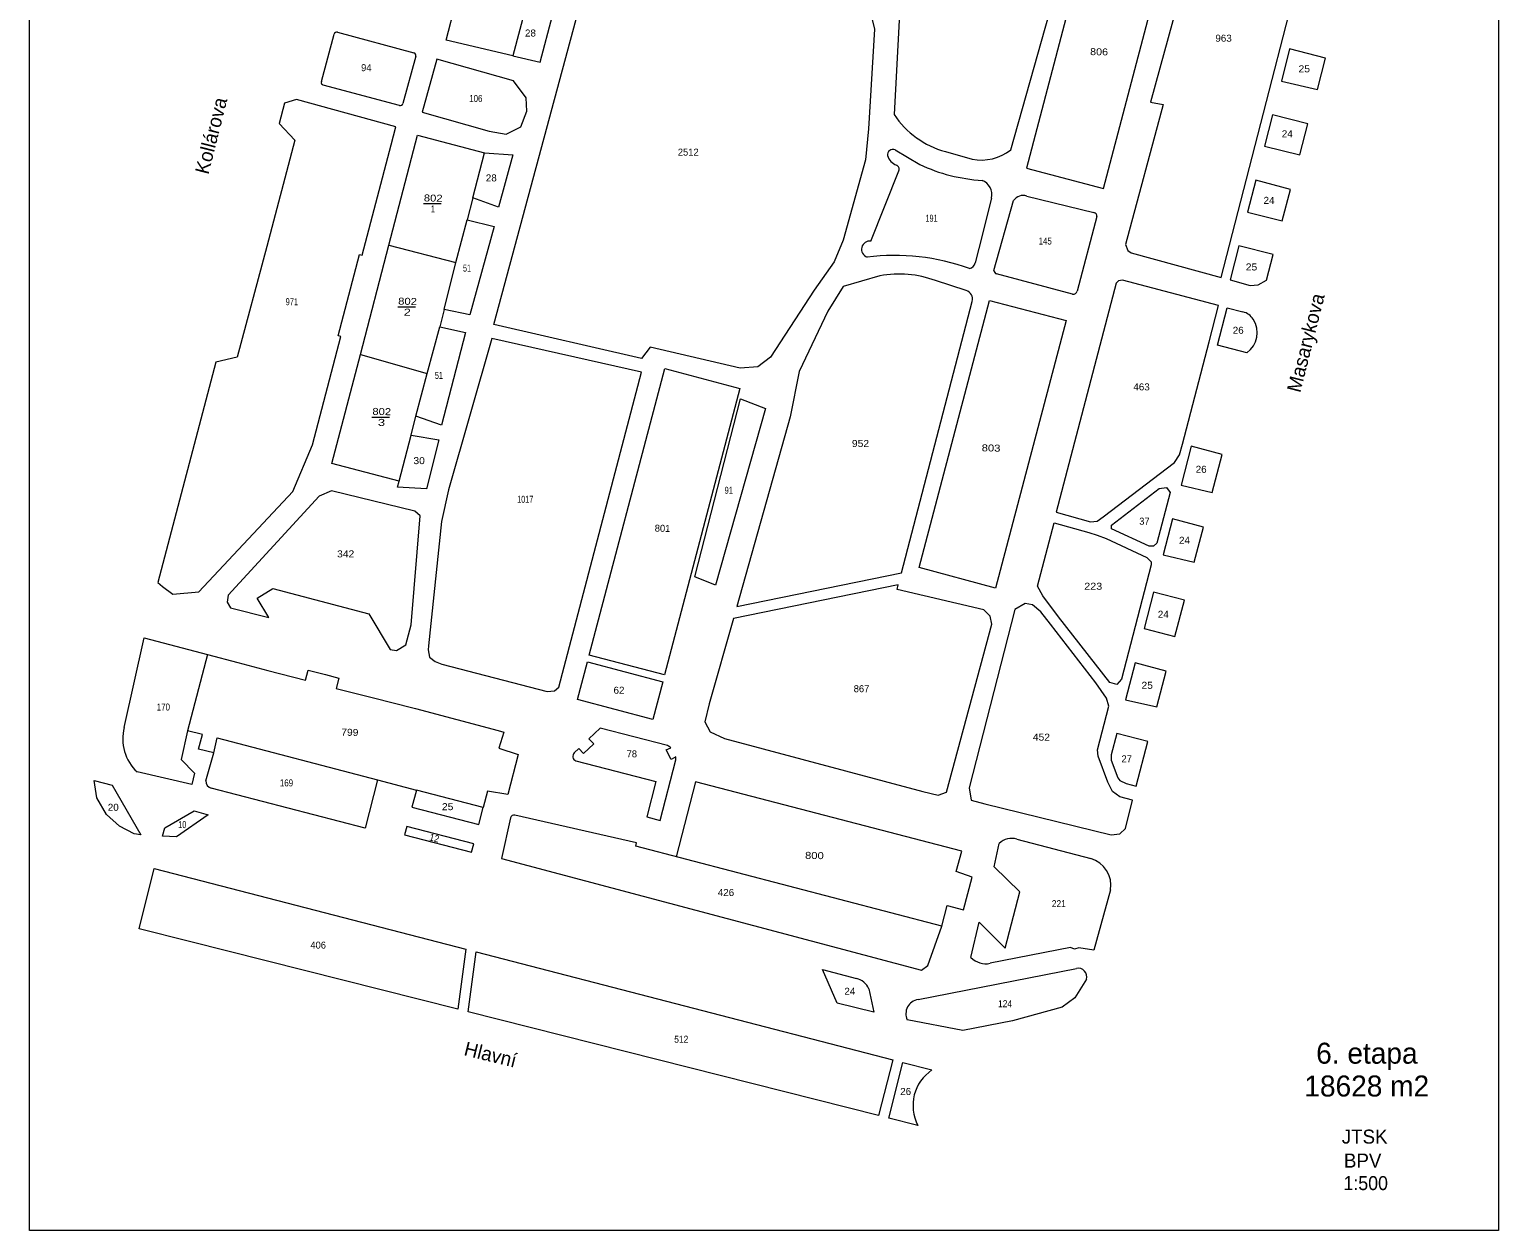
# Model space of a CAD drawing. Extents: x -843471 to -843261, y -1003203 to -1002905.
# Drawn here: x -843471 to -843261, y -1003202.7 to -1003031 of the extents above; entities that cross this region are included whole.
import ezdxf
from ezdxf.enums import TextEntityAlignment as Align

# ---------------------------------------------------------------- set-up
doc = ezdxf.new("R2010")
doc.units = 0
doc.header["$LTSCALE"] = 0.4
doc.layers.add('20', color=7, linetype='Continuous')
for name, color, linetype, lineweight in [('35', 7, 'Continuous', 13), ('38', 7, 'Continuous', 13), ('43', 7, 'Continuous', 13), ('44', 7, 'Continuous', 13), ('63', 7, 'Continuous', 13)]:
    doc.layers.add(name, color=color, linetype=linetype, lineweight=lineweight)

msp = doc.modelspace()

# ---------------------------------------------------------------- linework, layer by layer
at = {"layer": '35'}
for p, q in [((-843414.648, -1003055.883), (-843412.134, -1003055.883)), ((-843418.312, -1003070.638), (-843415.798, -1003070.638)), ((-843422.003, -1003086.395), (-843419.489, -1003086.395))]:
    msp.add_line(p, q, dxfattribs=at)
at = {"layer": '38'}
for p, q in [((-843415.48, -1003046.07), (-843405.92, -1003048.64)), ((-843407.59, -1003055.07), (-843408.4, -1003058.18)), ((-843419.59, -1003061.82), (-843410, -1003064.31)), ((-843411.69, -1003071.03), (-843412.32, -1003073.51)), ((-843423.66, -1003077.43), (-843414.12, -1003080.14)), ((-843416.41, -1003088.95), (-843415.71, -1003086.25)), ((-843421.233, -1003138.239), (-843415.655, -1003139.692))]:
    msp.add_line(p, q, dxfattribs=at)
for points in [[(-843401.85, -1003034.75), (-843411.41, -1003032.51), (-843407.25, -1003016.45), (-843403.17, -1003000.7), (-843399.16, -1002985.21), (-843389.38, -1002987.7)], [(-843418.13, -1003095.53), (-843427.74, -1003093.04), (-843423.66, -1003077.43), (-843419.59, -1003061.82), (-843415.48, -1003046.07)], [(-843445.52, -1003120.31), (-843441.17, -1003121.48), (-843436.9, -1003122.6), (-843431.5, -1003124.01), (-843431.12, -1003122.55), (-843428.65, -1003123.2), (-843426.72, -1003123.7), (-843427.1, -1003125.16), (-843421.38, -1003126.62), (-843419.36, -1003127.13), (-843415.77, -1003128.04), (-843403.96, -1003131.2), (-843403.16, -1003131.41), (-843403.87, -1003133.7), (-843401.1, -1003134.61), (-843402.58, -1003140.34), (-843405.473, -1003139.847), (-843406.09, -1003142.2)], [(-843444.62, -1003134.38), (-843446.8, -1003133.85), (-843446.21, -1003131.74), (-843448.38, -1003131.22)], [(-843340.54, -1003159.16), (-843339.77, -1003156.2), (-843337.44, -1003156.8), (-843336.19, -1003152.17), (-843338.49, -1003151.35), (-843337.67, -1003148.41), (-843375.75, -1003138.54), (-843378.53, -1003149.26)]]:
    msp.add_lwpolyline(points, dxfattribs=at)
for points in [[(-843328.45, -1003050.8), (-843317.44, -1003053.71), (-843307.34, -1003015.31), (-843311.55, -1003014.24), (-843314.18, -1003013.56), (-843318.38, -1003012.49)], [(-843333.74, -1003069.74), (-843322.76, -1003072.57), (-843332.86, -1003110.84), (-843343.79, -1003107.9)], [(-843380.17, -1003123.25), (-843390.96, -1003120.41), (-843380.61, -1003081.27), (-843380.13, -1003079.45), (-843369.44, -1003082.32)]]:
    msp.add_lwpolyline(points, close=True, dxfattribs=at)
at = {"layer": '43'}
for p, q in [((-843426.921, -1003031.39), (-843416.036, -1003034.326)), ((-843429.236, -1003038.434), (-843427.412, -1003031.672)), ((-843415.754, -1003034.816), (-843417.578, -1003041.578)), ((-843418.069, -1003041.86), (-843428.954, -1003038.924)), ((-843347.22, -1003048.18), (-843343.689, -1003050.295)), ((-843340.04, -1003048.43), (-843336.23, -1003049.51)), ((-843350.678, -1003061.242), (-843346.68, -1003051.19)), ((-843333.11, -1003065.43), (-843330.3, -1003055.45)), ((-843328.399, -1003054.801), (-843318.83, -1003057.14)), ((-843318.38, -1003057.71), (-843321.22, -1003068.4)), ((-843334.757, -1003060.227), (-843335.79, -1003064.36)), ((-843337.054, -1003068.297), (-843341.457, -1003066.878)), ((-843321.86, -1003068.82), (-843332.72, -1003065.92)), ((-843346.332, -1003108.655), (-843336.201, -1003069.851)), ((-843296.958, -1003077.188), (-843301.14, -1003076.09)), ((-843379.929, -1003133.964), (-843379.278, -1003133.638)), ((-843402.18, -1003143.65), (-843403.502, -1003149.498)), ((-843329.84, -1003146.7), (-843319.25, -1003149.5)), ((-843316.42, -1003153.97), (-843318.81, -1003162.58)), ((-843357.599, -1003165.361), (-843352.759, -1003166.612)), ((-843343.95, -1003169.65), (-843321.305, -1003165.185)), ((-843346.118, -1003178.626), (-843341.955, -1003179.704))]:
    msp.add_line(p, q, dxfattribs=at)
for points in [[(-843284.45, -1003003.7), (-843294.7, -1003000.64), (-843296.31, -1003001.22), (-843302.99, -1003013.24), (-843302.99, -1003013.24), (-843310.734, -1003041.383), (-843308.91, -1003041.72), (-843314.3, -1003061.74), (-843313.983, -1003062.586), (-843313.47, -1003062.92), (-843300.63, -1003066.44)], [(-843388.71, -1003014.29), (-843366.28, -1003020.43), (-843366.73, -1003022), (-843353.17, -1003025.55), (-843351, -1003027.64), (-843350.16, -1003030.95), (-843351.05, -1003045.19), (-843351.48, -1003049.64), (-843354.64, -1003061.08), (-843355.93, -1003064.18), (-843358.81, -1003068.24), (-843365.03, -1003077.8), (-843366.86, -1003079.21), (-843369.37, -1003079.38), (-843382.26, -1003076.4), (-843383.48, -1003078.02), (-843404.56, -1003073.14)], [(-843401.85, -1003034.75), (-843397.955, -1003035.663), (-843396.184, -1003028.978), (-843400.046, -1003027.953)], [(-843414.849, -1003042.812), (-843405.27, -1003045.53), (-843402.84, -1003045.94), (-843400.71, -1003044.91), (-843399.86, -1003042.66), (-843399.95, -1003040.76), (-843401.767, -1003038.337), (-843412.722, -1003035.254)], [(-843292.02, -1003038.36), (-843286.864, -1003039.586), (-843285.692, -1003035.093), (-843290.85, -1003033.77)], [(-843418.595, -1003044.919), (-843432.78, -1003041), (-843434.5, -1003041.54), (-843435.263, -1003044.448), (-843433.02, -1003046.81), (-843437.05, -1003062), (-843441.25, -1003077.83), (-843444.331, -1003078.56), (-843452.6, -1003110.03), (-843451.96, -1003110.61), (-843450.48, -1003111.71), (-843446.75, -1003111.38), (-843433.29, -1003097.02), (-843430.48, -1003090.34), (-843426.437, -1003074.888), (-843426.844, -1003074.782), (-843423.8, -1003063.15), (-843423.393, -1003063.256), (-843419.26, -1003047.46)], [(-843294.41, -1003047.68), (-843289.4, -1003048.9), (-843288.23, -1003044.49), (-843293.27, -1003043.2)], [(-843405.92, -1003048.64), (-843401.85, -1003048.89), (-843403.9, -1003056.39), (-843407.59, -1003055.07)], [(-843296.84, -1003057.1), (-843291.9, -1003058.32), (-843290.72, -1003053.87), (-843295.67, -1003052.53)], [(-843408.4, -1003058.18), (-843404.53, -1003059.14), (-843408.01, -1003071.76), (-843411.69, -1003071.03), (-843410, -1003064.31)], [(-843293.19, -1003063.17), (-843298.1, -1003061.92), (-843299.36, -1003066.78), (-843296.46, -1003067.56), (-843295.35, -1003067.49), (-843294.16, -1003066.84)], [(-843324.229, -1003099.954), (-843319.32, -1003101.34), (-843318.36, -1003101.24), (-843317.5, -1003100.634), (-843307.27, -1003092.87), (-843306.57, -1003091.79), (-843306.14, -1003090.26), (-843302.35, -1003075.63), (-843301.02, -1003070.45), (-843314.74, -1003066.83), (-843315.278, -1003066.897), (-843315.622, -1003067.26)], [(-843414.12, -1003080.14), (-843412.32, -1003073.51), (-843408.65, -1003074.31), (-843412.04, -1003087.56), (-843415.71, -1003086.25)], [(-843413.78, -1003120.71), (-843412.95, -1003121.33), (-843412.02, -1003121.68), (-843396.96, -1003125.61), (-843395.92, -1003125.51), (-843395.27, -1003124.99), (-843383.48, -1003079.99), (-843404.86, -1003075.14), (-843411.06, -1003096.77), (-843412.06, -1003101.33), (-843413.9, -1003119.1), (-843413.96, -1003119.64)], [(-843369.333, -1003083.797), (-843365.77, -1003085.15), (-843372.91, -1003110.39), (-843375.835, -1003109.243)], [(-843416.41, -1003088.95), (-843412.46, -1003089.64), (-843414.23, -1003096.66), (-843418.37, -1003096.41), (-843418.13, -1003095.53)], [(-843306.32, -1003096.1), (-843301.9, -1003097.17), (-843300.49, -1003091.73), (-843304.9, -1003090.56)], [(-843316.32, -1003102.34), (-843316.31, -1003101.85), (-843309.48, -1003096.59), (-843308.44, -1003096.44), (-843307.93, -1003097.18), (-843309.81, -1003104.42), (-843310.29, -1003104.84), (-843310.9, -1003104.86)], [(-843442.7, -1003112.85), (-843442.2, -1003113.65), (-843436.76, -1003115.04), (-843438.41, -1003112.27), (-843436.19, -1003110.91), (-843422.47, -1003114.51), (-843419.4, -1003119.61), (-843418.51, -1003119.73), (-843417.17, -1003118.92), (-843416.41, -1003116.09), (-843415.11, -1003100.52), (-843415.86, -1003099.84), (-843427.79, -1003096.94), (-843429.54, -1003097.71), (-843442.56, -1003111.82)], [(-843324.49, -1003101.48), (-843319.53, -1003102.9), (-843318.37, -1003103.25), (-843317.05, -1003103.75), (-843311.25, -1003106.46), (-843310.61, -1003107.08), (-843310.63, -1003107.51), (-843314.85, -1003123.86), (-843315.53, -1003124.6), (-843316.52, -1003124.32), (-843323.85, -1003114.96), (-843326.1, -1003111.92), (-843326.89, -1003110.55)], [(-843308.91, -1003106.06), (-843304.47, -1003107.12), (-843303.17, -1003102.11), (-843307.59, -1003100.91)], [(-843370.347, -1003115.171), (-843373.79, -1003127.38), (-843374.43, -1003129.93), (-843373.65, -1003131.37), (-843371.63, -1003132.33), (-843343.25, -1003139.88), (-843341.08, -1003140.44), (-843339.89, -1003140), (-843333.4, -1003115.97), (-843333.63, -1003114.83), (-843334.54, -1003113.93), (-843346.954, -1003111.038), (-843346.782, -1003110.379)], [(-843313.29, -1003141.15), (-843315.09, -1003140.66), (-843316.14, -1003139.9), (-843316.82, -1003138.56), (-843318.22, -1003134.85), (-843318.29, -1003133.97), (-843316.66, -1003127.71), (-843317.02, -1003126.54), (-843318.52, -1003124.37), (-843325.04, -1003116), (-843326.41, -1003114.24), (-843327.59, -1003113.23), (-843328.661, -1003113.027), (-843330.11, -1003113.91), (-843336.63, -1003139.36), (-843336.37, -1003141.15), (-843334.4, -1003141.67), (-843316.351, -1003146.08), (-843315.127, -1003145.939), (-843314.28, -1003145.19)], [(-843311.62, -1003116.6), (-843307.23, -1003117.75), (-843305.88, -1003112.55), (-843310.29, -1003111.39)], [(-843380.426, -1003124.217), (-843381.856, -1003129.626), (-843392.643, -1003126.773), (-843391.216, -1003121.377)], [(-843314.29, -1003126.79), (-843309.83, -1003127.81), (-843308.5, -1003122.68), (-843312.9, -1003121.52)], [(-843315.55, -1003131.61), (-843316.35, -1003134.68), (-843316.33, -1003135.43), (-843315.37, -1003137.97), (-843315.11, -1003138.31), (-843314.21, -1003138.77), (-843312.77, -1003139.14), (-843311.12, -1003132.77)], [(-843461.71, -1003138.35), (-843459.13, -1003138.99), (-843455.03, -1003146.09), (-843456.01, -1003145.97), (-843458.1, -1003144.87), (-843459.96, -1003143.19), (-843461.34, -1003140.83)], [(-843406.09, -1003142.2), (-843415.655, -1003139.692), (-843416.295, -1003142.132), (-843406.73, -1003144.64)], [(-843445.397, -1003143.229), (-843449.938, -1003146.368), (-843451.94, -1003146.29), (-843451.62, -1003145.1), (-843447.411, -1003142.685)], [(-843407.453, -1003147.399), (-843417.019, -1003144.89), (-843417.331, -1003146.082), (-843407.766, -1003148.59)], [(-843453.108, -1003150.917), (-843446.3, -1003152.68), (-843408.577, -1003162.45), (-843409.71, -1003171.023), (-843448.1, -1003161.33), (-843455.28, -1003159.517)], [(-843407.114, -1003162.829), (-843347.57, -1003178.25), (-843349.579, -1003186.206), (-843408.246, -1003171.393)]]:
    msp.add_lwpolyline(points, close=True, dxfattribs=at)
for points in [[(-843330.68, -1003048.19), (-843320.79, -1003013.05), (-843321.09, -1003011.86), (-843322.66, -1003011.55), (-843340.18, -1003010.64), (-843342.33, -1003011.23), (-843343.75, -1003012.82), (-843346.29, -1003023.32), (-843346.64, -1003029.65), (-843347.37, -1003043.16)], [(-843333.47, -1003055.08), (-843334.506, -1003059.225), (-843334.757, -1003060.227)], [(-843349.39, -1003066.18), (-843354.65, -1003067.73), (-843356.85, -1003071.23), (-843360.96, -1003079.89), (-843362.22, -1003086.35), (-843369.859, -1003113.439), (-843346.332, -1003108.655)], [(-843301.14, -1003076.09), (-843299.742, -1003070.764), (-843297.51, -1003071.35)], [(-843457.408, -1003130.736), (-843454.56, -1003117.95), (-843445.52, -1003120.31), (-843448.38, -1003131.22), (-843449.265, -1003135.312)], [(-843379.741, -1003133.34), (-843389.38, -1003130.857), (-843390.986, -1003132.384), (-843390.297, -1003133.109), (-843391.746, -1003134.487), (-843392.435, -1003133.762), (-843393.077, -1003134.372)], [(-843445.724, -1003138.384), (-843444.62, -1003134.38), (-843444.11, -1003132.23), (-843421.233, -1003138.239)], [(-843378.57, -1003134.961), (-843379.257, -1003135.305), (-843379.929, -1003133.964)], [(-843449.265, -1003135.312), (-843447.367, -1003137.265), (-843447.766, -1003138.888), (-843455.565, -1003137.108)], [(-843392.869, -1003135.521), (-843381.423, -1003138.47), (-843382.725, -1003143.527), (-843380.788, -1003144.026), (-843378.564, -1003135.391)], [(-843421.233, -1003138.239), (-843422.992, -1003145.123), (-843444.97, -1003139.41)], [(-843403.502, -1003149.498), (-843343.445, -1003165.446), (-843342.55, -1003164.79), (-843340.54, -1003159.16), (-843384.306, -1003147.723), (-843384.2, -1003147.26), (-843401.581, -1003143.275)], [(-843336.41, -1003163.63), (-843335.23, -1003158.59), (-843331.5, -1003162.3), (-843329.41, -1003154.24), (-843333.05, -1003150.65), (-843332.352, -1003147.312)], [(-843318.81, -1003162.58), (-843320.972, -1003162.24), (-843321.58, -1003162.46), (-843322.18, -1003162.21), (-843333.63, -1003164.46)], [(-843350.966, -1003168.096), (-843350.258, -1003171.421), (-843355.51, -1003170.166), (-843357.599, -1003165.361)], [(-843319.88, -1003166.73), (-843321.52, -1003169.41), (-843323.33, -1003170.71), (-843330.43, -1003172.68)], [(-843330.43, -1003172.68), (-843337.53, -1003174.06), (-843345.486, -1003172.535)], [(-843343.956, -1003187.626), (-843348.125, -1003186.574), (-843346.118, -1003178.626)]]:
    msp.add_lwpolyline(points, dxfattribs=at)
for centre, radius, start, end in [((-843427.0256, -1003031.7758), 0.4, 74.90421, 164.90421), ((-843416.1404, -1003034.712), 0.4, 344.90421, 74.90421), ((-843428.8496, -1003038.538), 0.4, 164.90421, 254.90421), ((-843417.9644, -1003041.4742), 0.4, 254.90421, 344.90421), ((-843336.6594, -1003035.9953), 12.8861, 213.77993, 254.79058), ((-843347.5123, -1003048.9279), 0.803, 68.65352, 186.5852), ((-843334.8795, -1003042.8592), 6.7863, 258.51965, 308.23051), ((-843346.3573, -1003048.4718), 2.0282, 195.68124, 250.18289), ((-843333.3754, -1003028.282), 24.3098, 244.89511, 266.64033), ((-843347.2545, -1003050.9615), 0.6182, 338.31208, 70.18289), ((-843335.5515, -1003054.5596), 2.1455, 345.96376, 69.49731), ((-843328.9497, -1003056.2978), 1.5944, 69.80983, 147.87639), ((-843318.9701, -1003057.7132), 0.5901, 0.31338, 76.26695), ((-843350.8442, -1003062.4124), 1.1823, 81.90379, 250.95449), ((-843347.2579, -1003094.4147), 31.1391, 69.96527, 97.32858), ((-843336.8567, -1003064.0933), 1.0995, 284.03624, 345.96376), ((-843346.7198, -1003081.2627), 15.3172, 69.90447, 100.03964), ((-843332.5843, -1003065.4118), 0.526, 181.98497, 255.04888), ((-843337.4525, -1003069.5262), 1.2924, 345.45708, 72.04952), ((-843321.7745, -1003068.2527), 0.5737, 261.42781, 345.12197), ((-843298.1488, -1003073.7852), 2.5176, 33.10949, 75.30064), ((-843298.9739, -1003074.3233), 3.5026, 305.13391, 33.10948), ((-843451.2342, -1003132.4031), 6.3951, 164.89169, 227.36989), ((-843380.6121, -1003135.2025), 2.0564, 49.55419, 64.92156), ((-843392.6097, -1003134.881), 0.6909, 132.52827, 247.94029), ((-843380.6121, -1003135.2025), 2.0564, 354.73873, 6.75686), ((-843444.7667, -1003138.4707), 0.961, 174.83771, 257.7865), ((-843401.6925, -1003143.7622), 0.5, 77.08604, 167.08604), ((-843330.5323, -1003149.3184), 2.7084, 75.18988, 132.21475), ((-843320.395, -1003153.3558), 4.0222, 351.21607, 73.46052), ((-843334.2309, -1003161.402), 3.1164, 225.63549, 281.11734), ((-843321.0669, -1003166.3948), 1.2333, 344.23012, 101.15547), ((-843353.5342, -1003169.3741), 2.8687, 26.45151, 74.31278), ((-843343.6632, -1003171.6539), 2.0244, 98.14547, 205.79684), ((-843338.5949, -1003184.7663), 6.076, 123.57723, 208.08087)]:
    msp.add_arc(centre, radius, start, end, dxfattribs=at)
at = {"layer": '44'}
msp.add_lwpolyline([(-843470.967, -1002904.664), (-843260.967, -1002904.664), (-843260.967, -1003202.664), (-843470.967, -1003202.664)], close=True, dxfattribs=at)
at = {"layer": '63'}
msp.add_line((-843346.782, -1003110.379), (-843370.347, -1003115.171), dxfattribs=at)

# ---------------------------------------------------------------- texts
at = {"layer": '20'}
for s, rotation, p in [('Kollárova', 75.846, (-843445.386, -1003051.808)), ('Masarykova', 75.858, (-843289.325, -1003082.996)), ('Hlavní', 346.137, (-843408.973, -1003177.566))]:
    msp.add_text(s, height=2, rotation=rotation, dxfattribs=at).set_placement(p)
at = {"layer": '35'}
for s, width, p in [('806', 1.15, (-843318.0845, -1003034.673)), ('802', 1.2, (-843413.259, -1003055.5859)), ('1', 0.7, (-843413.2945, -1003057.1358)), ('802', 1.2, (-843416.9245, -1003070.3409)), ('2', 1.35, (-843416.958, -1003071.8903)), ('802', 1.2, (-843420.6155, -1003086.0969)), ('3', 1.4, (-843420.6495, -1003087.6475)), ('803', 1.2, (-843333.524, -1003091.3041)), ('799', 1.1, (-843425.175, -1003131.9408)), ('800', 1.2, (-843358.7715, -1003149.5503))]:
    msp.add_text(s, height=1, rotation=358.734, dxfattribs=dict(at, width=width)).set_placement(p, align=Align.CENTER)
msp.add_text('801', height=1, rotation=358.734, dxfattribs=at).set_placement((-843380.477, -1003102.7805), align=Align.CENTER)
at = {"layer": '43'}
for s, width, p in [('28', 1.05, (-843400.13, -1003031.993)), ('963', 1.05, (-843301.454, -1003032.737)), ('25', 1.1, (-843289.565, -1003037.111)), ('106', 0.85, (-843408.107, -1003041.349)), ('24', 1.05, (-843291.955, -1003046.394)), ('28', 1.05, (-843405.725, -1003052.705)), ('24', 1.05, (-843294.561, -1003055.91)), ('191', 0.65, (-843342.889, -1003058.469)), ('145', 0.85, (-843326.722, -1003061.731)), ('51', 0.75, (-843408.991, -1003065.596)), ('25', 1.1, (-843297.102, -1003065.432)), ('971', 0.8, (-843434.342, -1003070.399)), ('26', 1.05, (-843298.967, -1003074.479)), ('51', 0.75, (-843413.014, -1003080.932)), ('463', 1.05, (-843313.173, -1003082.574)), ('952', 1.1, (-843353.402, -1003090.661)), ('30', 1.1, (-843416.079, -1003093.111)), ('26', 1.05, (-843304.261, -1003094.349)), ('91', 0.7, (-843371.597, -1003097.354)), ('1017', 0.75, (-843401.248, -1003098.636)), ('24', 1.05, (-843306.65, -1003104.495)), ('342', 1.1, (-843426.987, -1003106.441)), ('223', 1.15, (-843320.194, -1003111.067)), ('24', 1.05, (-843309.675, -1003115.075)), ('62', 1.05, (-843387.474, -1003125.928)), ('25', 1.1, (-843312.012, -1003125.224)), ('170', 0.85, (-843452.763, -1003128.326)), ('452', 1.1, (-843327.541, -1003132.631)), ('169', 0.85, (-843435.166, -1003139.174)), ('20', 1.05, (-843459.76, -1003142.658)), ('25', 1.1, (-843412.001, -1003142.57)), ('10', 0.75, (-843449.688, -1003145.135)), ('426', 1.05, (-843372.575, -1003154.837)), ('221', 0.9, (-843324.833, -1003156.43)), ('24', 1.05, (-843354.481, -1003168.955)), ('124', 0.9, (-843332.517, -1003170.732)), ('512', 0.9, (-843378.795, -1003175.811)), ('26', 1.05, (-843346.497, -1003183.274))]:
    msp.add_text(s, height=1, dxfattribs=dict(at, width=width)).set_placement(p)
for s, p in [('94', (-843423.554, -1003036.946)), ('2512', (-843378.283, -1003049.017)), ('37', (-843312.336, -1003101.769)), ('867', (-843353.144, -1003125.71)), ('78', (-843385.602, -1003135.026)), ('27', (-843314.868, -1003135.731)), ('406', (-843430.805, -1003162.359))]:
    msp.add_text(s, height=1, dxfattribs=at).set_placement(p)
at = {"layer": '43', "width": 0.95}
msp.add_text('12', height=1, rotation=345.306, dxfattribs=at).set_placement((-843413.891, -1003146.861))
at = {"layer": '44'}
for s, height, p in [('6. etapa', 3, (-843287.042, -1003178.806)), ('18628 m2', 3, (-843288.735, -1003183.494)), ('JTSK', 2, (-843283.383, -1003190.226)), ('BPV', 2, (-843283.073, -1003193.655))]:
    msp.add_text(s, height=height, dxfattribs=at).set_placement(p)
at = {"layer": '44', "width": 0.95}
msp.add_text('1:500', height=2, dxfattribs=at).set_placement((-843283.142, -1003196.873))

doc.saveas('drawing.dxf')
